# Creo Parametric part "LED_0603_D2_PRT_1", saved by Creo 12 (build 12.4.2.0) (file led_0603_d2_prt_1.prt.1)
Units: Custom; MM, KILOGRAM, SECS

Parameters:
  PTC_WM_ITERATION = "0"
  PTC_WM_VERSION = "-.0"
  PTC_WM_LIFECYCLE_STATE = "In Work"
  PTC_WM_LIFECYCLE = "MO_CADDocument"
  PTC_WM_CREATED_BY = "Maximilian Roepper (Z0017RMS: MO)"
  PTC_WM_CREATED_ON = "18-Sep-26 11:36:42 AM"
  PTC_WM_MODIFIED_BY = "Maximilian Roepper (Z0017RMS: MO)"
  PTC_WM_MODIFIED_ON = "18-Sep-26 11:36:46 AM"
  PDMLINKNUMBER = "PDM000071454906"
  PTC_WM_NAME = "led_0603_d2_prt_1.prt"
  PTC_WM_NUMBER = "PDM000071454906"

Other parameters: WEIGHT, WEIGHT_FACTOR, WEIGHT_ADD, _MASS_TEMP, _DIFF_TEMP, MC_ERRORS, SUPPLIER

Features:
  1. coordinate system
  2. datum plane "PRT_YZ"
  3. datum plane "PRT_XY"
  4. datum plane "PRT_XZ"
  5. coordinate system
  6. datum axis
  7. datum axis
  8. datum axis
  9. coordinate system
  10. imported feature
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
Other named items: PRT, SIEMENS_MO, DRW_VIEW_ORG, PRT_X, PRT_Y, PRT_Z, CS0, ROUGH_GROB

Layers: 00_STD_CSYS-KSYS, 01_STD_PLANES-EBENEN, 02_STD_AXES-ACHSEN, 03_STD_CSYS-KSYS, 24_IMPORT_FEAT-IMPORT_KE

Surfaces: 42 plane, 8 cylinder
